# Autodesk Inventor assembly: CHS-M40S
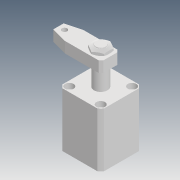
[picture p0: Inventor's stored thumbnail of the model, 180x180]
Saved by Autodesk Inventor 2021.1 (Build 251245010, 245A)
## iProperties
Created: 2019-04
Part Number: CHS-M40S
Description: STEP AP203
Document SubType Name: Assembly
Designer: user
Title: chs-m40s_asm.STEP
Revision Number: ÈÎºÎ
Sending System: SolidWorks 2017
Preprocessor: SwSTEP 2.0
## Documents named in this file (5)
- D:\Vault_2016\Projekty\Clamptek\Hydraulic\CHS\CHS-40\Inventor\CHS-M40S\CHS-M40S.iam
- D:\Vault_2016\Projekty\Clamptek\Hydraulic\CHS\CHS-40\Inventor\CHS-M40S\CHS-40S-02_4.ipt
- D:\Vault_2016\Projekty\Clamptek\Hydraulic\CHS\CHS-40\Inventor\CHS-M40S\CHS-40S-01_4.ipt
- D:\Vault_2016\Projekty\Clamptek\Hydraulic\CHS\CHS-40\Inventor\CHS-M40S\M18_4.ipt
- D:\Vault_2016\Projekty\Clamptek\Hydraulic\CHS\CHS-40\Inventor\CHS-M40S\CHS-M40BT.ipt
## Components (4 placed, 4 different names)
1. CHS-40S-02_4_1
2. CHS-40S-01_4_2
3. M18_4_3
4. CHS-M40BT_4
